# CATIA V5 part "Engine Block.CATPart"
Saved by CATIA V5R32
Part number: Part1
Bounding box of the stored display mesh (mm): x 0 to 150, y 0 to 40, z 0 to 43
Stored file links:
  D:\PROJECTS\Project 2022\CATIA V5 6R 2022\Resources\Input file\c19_catia_v5_6r2022_inp\c19_catia_v5_6r2022_inp\c19_catia_v5_6r2022_inp\C19_tut_04.CATPart\Engine Block.CATPart
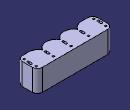
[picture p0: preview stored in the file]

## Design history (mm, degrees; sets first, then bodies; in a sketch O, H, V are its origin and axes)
Body1 (main body)
  Sketch1 on xy-plane, origin (0, 0, 0), H (1, 0, 0), V (0, 1, 0)
    line L1 (10, 0) -> (140, 0)
    line L2 (150, 10) -> (150, 30)
    line L3 (140, 40) -> (10, 40)
    line L4 (0, 30) -> (0, 10)
    arc A1 centre (10, 10) radius 10 from (10, 0) to (0, 10) cw
    arc A2 centre (140, 10) radius 10 from (140, 0) to (150, 10) ccw
    arc A3 centre (140, 30) radius 10 from (150, 30) to (140, 40) ccw
    arc A4 centre (10, 30) radius 10 from (10, 40) to (0, 30) ccw
    radius A1 = 10
    radius A2 = 10
    radius A3 = 10
    radius A4 = 10
    distance L2 L4 = 150
    distance L3 L1 = 40
    horizontal: L1 H, L3 H
    vertical: L2 V, L4 V
    coincidence: L1 O, L4 O
    tangency: A1 L1, A1 L4, A2 L1, A2 L2, A3 L2, A3 L3, A4 L3, A4 L4
  Pad1: profile Sketch1, direction (0, 0, 1), length 43
  Sketch2 on xy-plane, origin (0, 0, 0), H (1, 0, 0), V (0, 1, 0)
    circle A1 centre (22.5, 20) radius 12.5
    point P1 (22.5, 20)
    point P2 (57.5, 20)
    circle A2 centre (57.5, 20) radius 12.5
    point P3 (92.5, 20)
    circle A3 centre (92.5, 20) radius 12.5
    point P4 (127.5, 20)
    circle A4 centre (127.5, 20) radius 12.5
    reference projected line E1 (140, 40) -> (10, 40) from edge [face of Pad1 from Sketch1.L3 | end face of Pad1]
    construction line L1 (22.5, 20) -> (160.4972, 20)
    axis line L2 (75, 83.7885) -> (75, -11.6317)
    reference projected line E2 (150, 10) -> (150, 30) from edge [face of Pad1 from Sketch1.L2 | end face of Pad1]
    reference projected line E3 (0, 30) -> (0, 10) from edge [face of Pad1 from Sketch1.L4 | end face of Pad1]
    radius A2 = 12.5
    radius A3 = 12.5
    radius A4 = 12.5
    distance P1 E1 = 20
    distance P1 P2 = 35
    distance P2 P3 = 35
    distance P3 P4 = 35
    horizontal: L1 H
    coincidence: L1 P2, L1 P3, P4 L1
    symmetry: E2 E3 L2, A4 A1 L2
  Pocket1: profile Sketch2, direction (0, 0, 1), length 40
  Sketch3 on start face of Pad1, origin (0, 0, 0), H (1, 0, 0), V (0, -1, 0)
    arc A1 centre (22.5, -20) radius 20 from (40, -10.3175) to (22.4999, 0) ccw
    arc A2 centre (57.5, -20) radius 20 from (57.5, 0) to (40, -10.3175) ccw
    reference projected circle E1 centre (57.5, -20) radius 12.5 from edge [face of Pocket1 from Sketch2.A2 | start face of Pad1]
    reference projected circle E2 centre (22.5, -20) radius 12.5 from edge [face of Pocket1 from Sketch2.A1 | start face of Pad1]
    line L1 (22.4999, 0) -> (57.5, 0)
    radius A1 = 20
    radius A2 = 20
    concentricity: A2 E1, E2 A1
    fix: L1
  Pocket2: profile Sketch3, direction (0, 0, 1), through (limit type 6)
  RectPattern1: of Pocket2, direction 1 instances 3, spacing 35, along edge [start face of Pad1 | face of Pad1 from Sketch1.L1]
  Sketch4 on start face of Pad1, origin (0, 0, 0), H (1, 0, 0), V (0, -1, 0)
    circle A1 centre (6, -32) radius 2
    point P2 (40, -32)
    circle A2 centre (40, -32) radius 2
    point P3 (75, -32)
    circle A3 centre (75, -32) radius 2
    point P4 (110, -32)
    circle A4 centre (110, -32) radius 2
    circle A5 centre (144, -32) radius 2
    construction line L1 (6, -32) -> (144, -32)
    construction line L2 (40, 4.6658) -> (40, -59.1562)
    reference projected point E1 (40, -10.3175) from vertex [start face of Pad1 | face of Pocket2 from Sketch3.A2 | face of Pocket2 from Sketch3.A1]
    construction line L3 (110, 9.612) -> (110, -55.4864)
    construction line L4 (75, 52.0631) -> (75, -75.4722)
    reference projected line E2 (0, -30) -> (0, -10) from edge [start face of Pad1 | face of Pad1 from Sketch1.L4]
    reference projected line E3 (150, -10) -> (150, -30) from edge [start face of Pad1 | face of Pad1 from Sketch1.L2]
    reference projected point E4 (110, -10.3175) from vertex [face of RectPattern1 | face of RectPattern1 | start face of Pad1]
    axis line L5 (-9.2648, -20) -> (155.2665, -20)
    reference projected line E5 (10, 0) -> (140, 0) from edge [start face of Pad1 | face of Pad1 from Sketch1.L1]
    reference projected line E6 (140, -40) -> (10, -40) from edge [start face of Pad1 | face of Pad1 from Sketch1.L3]
    circle A6 centre (6, -8) radius 2
    circle A7 centre (144, -8) radius 2
    radius A1 = 2
    radius A2 = 2
    radius A3 = 2
    radius A4 = 2
    horizontal: L1 H, L5 H
    coincidence: P4 L1, P3 L1, P2 L1, L2 E1, P2 L2, P4 L3, P3 L4, L3 E4
    vertical: L2 V, L3 V, L4 V
    symmetry: E2 E3 L4, A1 A5 L4, E5 E6 L5, A1 A6 L5, A5 A7 L5
    fix: A1
  Pocket3: profile Sketch4, direction (0, 0, 1), through (limit type 6)
  Sketch5 on start face of Pad1, origin (0, 0, 0), H (1, 0, 0), V (0, -1, 0)
    construction line L1 (40, -22.3175) -> (40, -16.3175)
    point P2 (40, -16.3175)
    line L2 (38, -22.3175) -> (38, -16.3175)
    line L3 (42, -16.3175) -> (42, -22.3175)
    arc A1 centre (40, -16.3175) radius 2 from (38, -16.3175) to (42, -16.3175) cw
    arc A2 centre (40, -22.3175) radius 2 from (42, -22.3175) to (38, -22.3175) cw
    point P3 (38, -22.3175)
    point P4 (38, -16.3175)
    point P5 (42, -16.3175)
    point P6 (42, -22.3175)
    reference projected point E1 (40, -10.3175) from vertex [start face of Pad1 | face of Pocket2 from Sketch3.A2 | face of Pocket2 from Sketch3.A1]
    reference projected point E2 (40, -10.3175) from vertex [start face of Pad1 | face of Pocket2 from Sketch3.A2 | face of Pocket2 from Sketch3.A1]
    point P7 (75, -16.3175)
    point P8 (75, -22.3175)
    construction line L4 (75, -22.3175) -> (75, -16.3175)
    point P9 (73, -22.3175)
    point P10 (73, -16.3175)
    point P11 (77, -16.3175)
    point P12 (77, -22.3175)
    line L5 (73, -22.3175) -> (73, -16.3175)
    line L6 (77, -16.3175) -> (77, -22.3175)
    arc A3 centre (75, -16.3175) radius 2 from (73, -16.3175) to (77, -16.3175) cw
    arc A4 centre (75, -22.3175) radius 2 from (77, -22.3175) to (73, -22.3175) cw
    reference projected point E3 (75, -10.3175) from vertex [face of RectPattern1 | face of RectPattern1 | start face of Pad1]
    construction line L7 (110, -22.3175) -> (110, -16.3175)
    point P15 (112, -22.3175)
    point P16 (112, -16.3175)
    point P17 (108, -16.3175)
    point P18 (108, -22.3175)
    line L8 (112, -22.3175) -> (112, -16.3175)
    line L9 (108, -16.3175) -> (108, -22.3175)
    arc A5 centre (110, -16.3175) radius 2 from (112, -16.3175) to (108, -16.3175) ccw
    arc A6 centre (110, -22.3175) radius 2 from (108, -22.3175) to (112, -22.3175) ccw
    reference projected point E4 (75, -10.3175) from vertex [face of RectPattern1 | face of RectPattern1 | start face of Pad1]
    axis line L10 (40, -22.3175) -> (110, -22.3175)
    construction line L11 (5, -22.3175) -> (5, -16.3175)
    point P21 (7, -22.3175)
    point P22 (7, -16.3175)
    point P23 (3, -16.3175)
    point P24 (3, -22.3175)
    line L12 (7, -22.3175) -> (7, -16.3175)
    line L13 (3, -16.3175) -> (3, -22.3175)
    arc A7 centre (5, -16.3175) radius 2 from (7, -16.3175) to (3, -16.3175) ccw
    arc A8 centre (5, -22.3175) radius 2 from (3, -22.3175) to (7, -22.3175) ccw
    construction line L14 (145, -22.3175) -> (145, -16.3175)
    point P27 (147, -22.3175)
    point P28 (147, -16.3175)
    point P29 (143, -16.3175)
    point P30 (143, -22.3175)
    line L15 (147, -22.3175) -> (147, -16.3175)
    line L16 (143, -16.3175) -> (143, -22.3175)
    arc A9 centre (145, -16.3175) radius 2 from (147, -16.3175) to (143, -16.3175) ccw
    arc A10 centre (145, -22.3175) radius 2 from (143, -22.3175) to (147, -22.3175) ccw
    distance L1 L2 = 2
    length L1 = 6
    distance P2 E2 = 6
    distance P7 E4 = 6
    radius A3 = 2
    distance L5 L6 = 4
    vertical: L1 V
    tangency: A1 L2, A2 L2, A1 L3, A2 L3
    coincidence: L1 E1, L4 E3, L10 P8
    symmetry: L1 L7 L4, P3 P15 L4, P4 P16 L4, P5 P17 L4, P6 P18 L4, L2 L8 L4, L3 L9 L4, A1 A5 L4, A2 A6 L4, L4 L11 L1, P9 P21 L1, P10 P22 L1, P11 P23 L1, P12 P24 L1, L5 L12 L1, L6 L13 L1, A3 A7 L1, A4 A8 L1, L4 L14 L7, P9 P27 L7, P10 P28 L7, P11 P29 L7, P12 P30 L7, L5 L15 L7, L6 L16 L7, A3 A9 L7, A4 A10 L7
    horizontal: L10 H
  Pocket4: profile Sketch5, direction (0, 0, 1), through (limit type 6)
  Sketch6 on start face of Pad1, origin (0, 0, 0), H (1, 0, 0), V (0, -1, 0)
    construction line L1 (-2.1155, -20) -> (152.3983, -20)
    reference projected line E1 (10, 0) -> (140, 0) from edge [start face of Pad1 | face of Pad1 from Sketch1.L1]
    reference projected line E2 (140, -40) -> (10, -40) from edge [start face of Pad1 | face of Pad1 from Sketch1.L3]
    circle A1 centre (22, -4) radius 1.5
    point P3 (22, -4)
    circle A2 centre (22, -36) radius 1.5
    construction line L2 (40, 18.8361) -> (40, -51.6721)
    reference projected point E3 (40, -10.3175) from vertex [start face of Pad1 | face of RectPattern1 | face of Pocket2 from Sketch3.A1]
    circle A3 centre (58, -4) radius 1.5
    axis line L3 (75, 12.6867) -> (75, -50.2038)
    reference projected point E4 (75, -10.3175) from vertex [face of RectPattern1 | face of RectPattern1 | start face of Pad1]
    circle A4 centre (58, -36) radius 1.5
    circle A5 centre (128, -4) radius 1.5
    circle A6 centre (128, -36) radius 1.5
    circle A7 centre (92, -36) radius 1.5
    circle A8 centre (92, -4) radius 1.5
    radius A1 = 1.5
    distance P3 V = 22
    distance P3 L1 = 16
    horizontal: L1 H
    symmetry: E1 E2 L1, A1 A2 L1, A1 A3 L2, A2 A4 L2, A1 A5 L3, A2 A6 L3, A4 A7 L3, A3 A8 L3
    vertical: L2 V, L3 V
    coincidence: E3 L2, L3 E4
  Pocket5: profile Sketch6, direction (0, 0, 1), length 10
